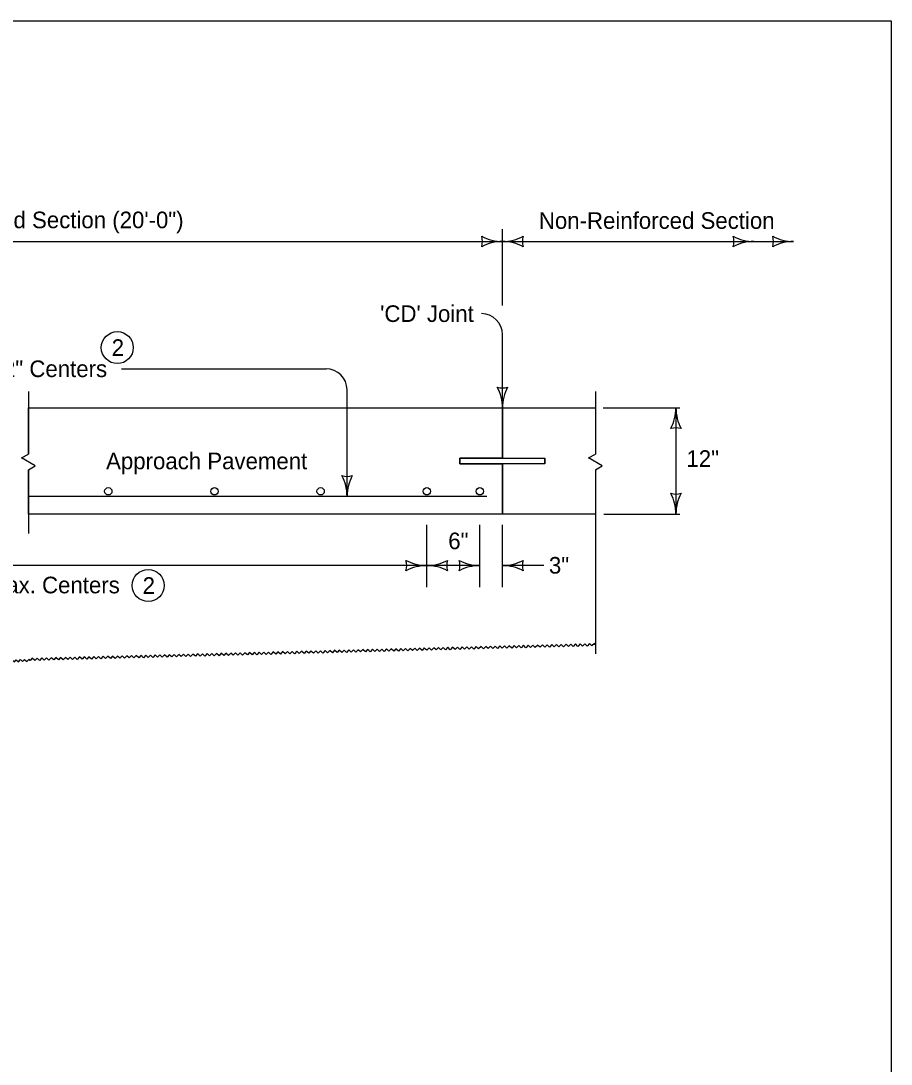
# Model space of a CAD drawing. Extents: x -2134934 to -2124557, y -2139046 to -2134021.
# Drawn here: x -2132638 to -2131799, y -2138041 to -2137036 of the extents above; entities that cross this region are included whole.
import ezdxf

# ---------------------------------------------------------------- set-up
doc = ezdxf.new("R2010")
doc.units = 0
for name, color, linetype in [('BridgeSuperStructureExisting', 7, 'Continuous'), ('dsnAlignmentStation', 7, 'Continuous'), ('dsnCellElements', 7, 'Continuous'), ('dsnStdLabel', 7, 'Continuous')]:
    doc.layers.add(name, color=color, linetype=linetype)

msp = doc.modelspace()

# ---------------------------------------------------------------- linework, layer by layer
at = {"layer": 'BridgeSuperStructureExisting'}
for p, q in [((-2132630.7, -2137393.1), (-2132630.7, -2137453.2)), ((-2132084.4, -2137393.1), (-2132084.4, -2137453.2)), ((-2132174, -2137457.1), (-2132174, -2137408.7)), ((-2132214.9, -2137462.7), (-2132214.9, -2137457.1)), ((-2132214.9, -2137457.1), (-2132133.1, -2137457.1)), ((-2132133.1, -2137457.1), (-2132133.1, -2137462.7)), ((-2132630.7, -2137468.3), (-2132630.7, -2137529.9)), ((-2132133.1, -2137462.7), (-2132214.9, -2137462.7)), ((-2132174, -2137511), (-2132174, -2137462.7)), ((-2132084.4, -2137468.3), (-2132084.4, -2137645.6)), ((-2132189.1, -2137494), (-2132630.7, -2137494))]:
    msp.add_line(p, q, dxfattribs=at)
for points in [[(-2132630.7, -2137468.3), (-2132624.1, -2137464.6), (-2132637.3, -2137457), (-2132630.7, -2137453.2)], [(-2132084.4, -2137468.3), (-2132077.9, -2137464.6), (-2132091, -2137457), (-2132084.4, -2137453.2)]]:
    msp.add_lwpolyline(points, dxfattribs=at)
for centre, radius in [((-2132545.1, -2137350.7), 15.4), ((-2132553.8, -2137489.1), 3.55), ((-2132451.5, -2137489.1), 3.55), ((-2132349.2, -2137489.1), 3.55), ((-2132246.9, -2137489.1), 3.55), ((-2132195.8, -2137489.1), 3.55), ((-2132515.3, -2137579.9), 15.4)]:
    msp.add_circle(centre, radius, dxfattribs=at)
for centre, radius, start, end in [((-2132049.3, -2137408.7), 42.5, 331.9275, 360), ((-2132049.3, -2137408.7), 42.5, 331.9275, 360), ((-2131964.3, -2137408.7), 42.5, 180, 208.0725), ((-2131964.3, -2137408.7), 42.5, 180, 208.0725), ((-2132006.8, -2137444.4), 16.4, 72.2666, 107.7334), ((-2132006.8, -2137444.4), 16.4, 72.2666, 107.7334), ((-2132006.8, -2137475.4), 16.4, 252.2666, 287.7333), ((-2132049.3, -2137511), 42.5, 360, 28.0725), ((-2131964.3, -2137511), 42.5, 151.9275, 180)]:
    msp.add_arc(centre, radius, start, end, dxfattribs=at)
at = {"layer": 'dsnAlignmentStation'}
msp.add_lwpolyline([(-2134934.4, -2137035.9), (-2131799.4, -2137035.9), (-2131799.4, -2139045.9), (-2134934.4, -2139045.9)], close=True, dxfattribs=at)
at = {"layer": 'dsnCellElements'}
for centre, radius, start, end in [((-2132209.6, -2137248.5), 16.4, 342.2666, 17.7333), ((-2132174, -2137206), 42.5, 241.9275, 270), ((-2132174, -2137291), 42.5, 90, 118.0725), ((-2132174, -2137206), 42.5, 270, 298.0725), ((-2132174, -2137291), 42.5, 61.9275, 90), ((-2132138.4, -2137248.5), 16.4, 162.2666, 197.7334), ((-2131967.3, -2137248.5), 16.4, 342.2666, 17.7333), ((-2131931.7, -2137206), 42.5, 241.9275, 270), ((-2131931.7, -2137291), 42.5, 90, 118.0725), ((-2131929.2, -2137248.5), 16.4, 342.2666, 17.7333), ((-2131893.5, -2137206), 42.5, 241.9275, 270), ((-2131893.5, -2137291), 42.5, 90, 118.0725), ((-2132174, -2137373.1), 16.4, 252.2666, 287.7333), ((-2132216.5, -2137408.7), 42.5, 360, 28.0725), ((-2132131.5, -2137408.7), 42.5, 151.9275, 180), ((-2132323.7, -2137458.4), 16.4, 252.2666, 287.7333), ((-2132366.2, -2137494), 42.5, 360, 28.0725), ((-2132281.2, -2137494), 42.5, 151.9275, 180), ((-2132282.6, -2137560.7), 16.4, 342.2666, 17.7333), ((-2132246.9, -2137518.2), 42.5, 241.9275, 270), ((-2132246.9, -2137518.2), 42.5, 270, 298.0725), ((-2132211.3, -2137560.7), 16.4, 162.2666, 197.7334), ((-2132231.4, -2137560.7), 16.4, 342.2666, 17.7333), ((-2132195.8, -2137518.2), 42.5, 241.9275, 270), ((-2132174, -2137518.2), 42.5, 270, 298.0725), ((-2132138.4, -2137560.7), 16.4, 162.2666, 197.7334), ((-2132246.9, -2137603.2), 42.5, 90, 118.0725), ((-2132246.9, -2137603.2), 42.5, 61.9275, 90), ((-2132195.8, -2137603.2), 42.5, 90, 118.0725), ((-2132174, -2137603.2), 42.5, 61.9275, 90)]:
    msp.add_arc(centre, radius, start, end, dxfattribs=at)
at = {"layer": 'dsnStdLabel'}
for p, q in [((-2132174, -2137310.2), (-2132174, -2137236.5)), ((-2133142.6, -2137248.5), (-2132174, -2137248.5)), ((-2132174, -2137248.5), (-2131893.5, -2137248.5)), ((-2132174, -2137408.7), (-2132174, -2137338.2)), ((-2132541, -2137371.1), (-2132343.9, -2137371.1)), ((-2132323.7, -2137494), (-2132323.7, -2137391.3)), ((-2132630.7, -2137453.2), (-2132630.7, -2137408.7)), ((-2132630.7, -2137408.7), (-2132174, -2137408.7)), ((-2132630.7, -2137408.7), (-2132174, -2137408.7)), ((-2132174, -2137408.7), (-2132174, -2137457.1)), ((-2132174, -2137408.7), (-2132084.9, -2137408.7)), ((-2132076.8, -2137408.7), (-2132003, -2137408.7)), ((-2132006.8, -2137408.7), (-2132006.8, -2137511)), ((-2132630.7, -2137453.2), (-2132630.7, -2137453.2)), ((-2132174, -2137457.1), (-2132214.9, -2137457.1)), ((-2132214.9, -2137457.1), (-2132214.9, -2137462.7)), ((-2132214.9, -2137457.1), (-2132214.9, -2137462.7)), ((-2132133.1, -2137462.7), (-2132133.1, -2137457.1)), ((-2132630.7, -2137511), (-2132630.7, -2137468.3)), ((-2132214.9, -2137462.7), (-2132174, -2137462.7)), ((-2132174, -2137462.7), (-2132174, -2137511)), ((-2132174, -2137511), (-2132174, -2137462.7)), ((-2132174, -2137511), (-2132630.7, -2137511)), ((-2132174, -2137511), (-2132630.7, -2137511)), ((-2132084.4, -2137511), (-2132174, -2137511)), ((-2132076.3, -2137511), (-2132003, -2137511)), ((-2132246.9, -2137581.5), (-2132246.9, -2137521.5)), ((-2132195.8, -2137581.5), (-2132195.8, -2137521.5)), ((-2132174, -2137581.5), (-2132174, -2137521.5)), ((-2132246.9, -2137560.7), (-2133069.7, -2137560.7)), ((-2132195.8, -2137560.7), (-2132246.9, -2137560.7)), ((-2132134.2, -2137560.7), (-2132174, -2137560.7))]:
    msp.add_line(p, q, dxfattribs=at)
for points in [[(-2132630.7, -2137468.3), (-2132624.1, -2137464.6), (-2132637.3, -2137457), (-2132630.7, -2137453.2)], [(-2132248.1, -2137641.2), (-2132249.3, -2137640), (-2132251.5, -2137642.4), (-2132253.8, -2137640.2), (-2132256, -2137642.5), (-2132258.4, -2137640.3), (-2132260.6, -2137642.6), (-2132262.9, -2137640.4), (-2132265.1, -2137642.7), (-2132267.5, -2137640.5), (-2132269.7, -2137642.8), (-2132272, -2137640.6), (-2132274.2, -2137643), (-2132276.6, -2137640.8), (-2132278.8, -2137643.1), (-2132281.1, -2137640.9), (-2132283.3, -2137643.2), (-2132285.7, -2137641), (-2132287.9, -2137643.3), (-2132290.2, -2137641.1), (-2132292.4, -2137643.4), (-2132294.8, -2137641.2), (-2132297, -2137643.6), (-2132299.3, -2137641.3), (-2132301.5, -2137643.7), (-2132302.7, -2137642.6)], [(-2132193.5, -2137639.7), (-2132194.6, -2137638.6), (-2132196.9, -2137640.9), (-2132199.2, -2137638.7), (-2132201.4, -2137641.1), (-2132203.8, -2137638.9), (-2132206, -2137641.2), (-2132208.3, -2137639), (-2132210.5, -2137641.3), (-2132212.9, -2137639.1), (-2132215.1, -2137641.4), (-2132217.4, -2137639.2), (-2132219.6, -2137641.5), (-2132222, -2137639.3), (-2132224.2, -2137641.7), (-2132226.5, -2137639.4), (-2132228.7, -2137641.8), (-2132231.1, -2137639.6), (-2132233.3, -2137641.9), (-2132235.6, -2137639.7), (-2132237.8, -2137642), (-2132240.2, -2137639.8), (-2132242.4, -2137642.1), (-2132244.7, -2137639.9), (-2132246.9, -2137642.2), (-2132248.1, -2137641.2)], [(-2132138.9, -2137638.3), (-2132140, -2137637.2), (-2132142.3, -2137639.5), (-2132144.6, -2137637.3), (-2132146.8, -2137639.6), (-2132149.1, -2137637.4), (-2132151.4, -2137639.8), (-2132153.7, -2137637.5), (-2132155.9, -2137639.9), (-2132158.2, -2137637.7), (-2132160.5, -2137640), (-2132162.8, -2137637.8), (-2132165, -2137640.1), (-2132167.4, -2137637.9), (-2132169.6, -2137640.2), (-2132171.9, -2137638), (-2132174.1, -2137640.3), (-2132176.4, -2137638.1), (-2132178.7, -2137640.5), (-2132181, -2137638.3), (-2132183.2, -2137640.6), (-2132185.5, -2137638.4), (-2132187.8, -2137640.7), (-2132190.1, -2137638.5), (-2132192.3, -2137640.8), (-2132193.5, -2137639.7)], [(-2132084.3, -2137636.9), (-2132085.4, -2137635.8), (-2132087.7, -2137638.1), (-2132090, -2137635.9), (-2132092.2, -2137638.2), (-2132094.5, -2137636), (-2132096.8, -2137638.3), (-2132099.1, -2137636.1), (-2132101.3, -2137638.5), (-2132103.6, -2137636.2), (-2132105.9, -2137638.6), (-2132108.2, -2137636.4), (-2132110.4, -2137638.7), (-2132112.7, -2137636.5), (-2132115, -2137638.8), (-2132117.3, -2137636.6), (-2132119.5, -2137638.9), (-2132121.8, -2137636.7), (-2132124.1, -2137639), (-2132126.4, -2137636.8), (-2132128.6, -2137639.2), (-2132130.9, -2137637), (-2132133.2, -2137639.3), (-2132135.5, -2137637.1), (-2132137.7, -2137639.4), (-2132138.9, -2137638.3)], [(-2132575.7, -2137649.7), (-2132576.9, -2137648.6), (-2132579.1, -2137650.9), (-2132581.5, -2137648.7), (-2132583.7, -2137651), (-2132586, -2137648.8), (-2132588.2, -2137651.2), (-2132590.6, -2137649), (-2132592.8, -2137651.3), (-2132595.1, -2137649.1), (-2132597.3, -2137651.4), (-2132599.7, -2137649.2), (-2132601.9, -2137651.5), (-2132604.2, -2137649.3), (-2132606.4, -2137651.6), (-2132608.8, -2137649.4), (-2132611, -2137651.8), (-2132613.3, -2137649.5), (-2132615.5, -2137651.9), (-2132617.9, -2137649.7), (-2132620.1, -2137652), (-2132622.4, -2137649.8), (-2132624.6, -2137652.1), (-2132627, -2137649.9), (-2132629.2, -2137652.2), (-2132630.3, -2137651.1)], [(-2132521.1, -2137648.3), (-2132522.3, -2137647.2), (-2132524.5, -2137649.5), (-2132526.8, -2137647.3), (-2132529.1, -2137649.6), (-2132531.4, -2137647.4), (-2132533.6, -2137649.7), (-2132535.9, -2137647.5), (-2132538.2, -2137649.9), (-2132540.5, -2137647.6), (-2132542.7, -2137650), (-2132545, -2137647.8), (-2132547.3, -2137650.1), (-2132549.6, -2137647.9), (-2132551.8, -2137650.2), (-2132554.1, -2137648), (-2132556.4, -2137650.3), (-2132558.7, -2137648.1), (-2132560.9, -2137650.5), (-2132563.2, -2137648.2), (-2132565.5, -2137650.6), (-2132567.8, -2137648.4), (-2132570, -2137650.7), (-2132572.4, -2137648.5), (-2132574.6, -2137650.8), (-2132575.7, -2137649.7)], [(-2132466.5, -2137646.8), (-2132467.7, -2137645.7), (-2132469.9, -2137648.1), (-2132472.2, -2137645.9), (-2132474.5, -2137648.2), (-2132476.8, -2137646), (-2132479, -2137648.3), (-2132481.3, -2137646.1), (-2132483.6, -2137648.4), (-2132485.9, -2137646.2), (-2132488.1, -2137648.6), (-2132490.4, -2137646.3), (-2132492.7, -2137648.7), (-2132495, -2137646.5), (-2132497.2, -2137648.8), (-2132499.5, -2137646.6), (-2132501.8, -2137648.9), (-2132504.1, -2137646.7), (-2132506.3, -2137649), (-2132508.6, -2137646.8), (-2132510.9, -2137649.1), (-2132513.2, -2137646.9), (-2132515.4, -2137649.3), (-2132517.7, -2137647.1), (-2132520, -2137649.4), (-2132521.1, -2137648.3)], [(-2132411.9, -2137645.4), (-2132413.1, -2137644.3), (-2132415.3, -2137646.6), (-2132417.6, -2137644.4), (-2132419.8, -2137646.8), (-2132422.2, -2137644.6), (-2132424.4, -2137646.9), (-2132426.7, -2137644.7), (-2132428.9, -2137647), (-2132431.3, -2137644.8), (-2132433.5, -2137647.1), (-2132435.8, -2137644.9), (-2132438, -2137647.2), (-2132440.4, -2137645), (-2132442.6, -2137647.4), (-2132444.9, -2137645.2), (-2132447.1, -2137647.5), (-2132449.5, -2137645.3), (-2132451.7, -2137647.6), (-2132454, -2137645.4), (-2132456.3, -2137647.7), (-2132458.6, -2137645.5), (-2132460.8, -2137647.8), (-2132463.1, -2137645.6), (-2132465.4, -2137648), (-2132466.5, -2137646.8)], [(-2132357.3, -2137644), (-2132358.5, -2137642.9), (-2132360.7, -2137645.2), (-2132363, -2137643), (-2132365.2, -2137645.3), (-2132367.6, -2137643.1), (-2132369.8, -2137645.5), (-2132372.1, -2137643.2), (-2132374.3, -2137645.6), (-2132376.7, -2137643.4), (-2132378.9, -2137645.7), (-2132381.2, -2137643.5), (-2132383.4, -2137645.8), (-2132385.8, -2137643.6), (-2132388, -2137645.9), (-2132390.3, -2137643.7), (-2132392.5, -2137646.1), (-2132394.9, -2137643.8), (-2132397.1, -2137646.2), (-2132399.4, -2137644), (-2132401.6, -2137646.3), (-2132404, -2137644.1), (-2132406.2, -2137646.4), (-2132408.5, -2137644.2), (-2132410.7, -2137646.5), (-2132411.9, -2137645.4)], [(-2132302.7, -2137642.6), (-2132303.9, -2137641.5), (-2132306.1, -2137643.8), (-2132308.4, -2137641.6), (-2132310.6, -2137643.9), (-2132313, -2137641.7), (-2132315.2, -2137644), (-2132317.5, -2137641.8), (-2132319.7, -2137644.2), (-2132322.1, -2137641.9), (-2132324.3, -2137644.3), (-2132326.6, -2137642.1), (-2132328.8, -2137644.4), (-2132331.2, -2137642.2), (-2132333.4, -2137644.5), (-2132335.7, -2137642.3), (-2132337.9, -2137644.6), (-2132340.3, -2137642.4), (-2132342.5, -2137644.7), (-2132344.8, -2137642.5), (-2132347, -2137644.9), (-2132349.4, -2137642.7), (-2132351.6, -2137645), (-2132353.9, -2137642.8), (-2132356.1, -2137645.1), (-2132357.3, -2137644)], [(-2132667, -2137652.9), (-2132666.2, -2137652), (-2132664.1, -2137653.9), (-2132662.2, -2137651.9), (-2132660.2, -2137653.8), (-2132658.2, -2137651.8), (-2132656.2, -2137653.7), (-2132654.3, -2137651.7), (-2132652.2, -2137653.6), (-2132650.3, -2137651.6), (-2132648.3, -2137653.5), (-2132646.3, -2137651.5), (-2132644.3, -2137653.4), (-2132642.4, -2137651.4), (-2132640.3, -2137653.3), (-2132638.4, -2137651.3), (-2132636.4, -2137653.2), (-2132634.4, -2137651.2), (-2132632.4, -2137653.1), (-2132630.5, -2137651), (-2132629.5, -2137652)]]:
    msp.add_lwpolyline(points, dxfattribs=at)
for centre in [(-2132194.2, -2137338.2), (-2132343.9, -2137391.3)]:
    msp.add_arc(centre, 20.2, 0, 90, dxfattribs=at)

# ---------------------------------------------------------------- texts
for s, p in [('Single Reinforced Section (20\'-0")', (-2132802.1, -2137235.7)), ('Non-Reinforced Section', (-2132138.9, -2137236.3)), ("'CD' Joint", (-2132291.8, -2137326)), ('2', (-2132550.5, -2137358.7)), ('#5 Bars At 12" Centers', (-2132773, -2137379.1)), ('12"', (-2131996.7, -2137465.6)), ('Approach Pavement', (-2132555.9, -2137467.9)), ('6"', (-2132226.2, -2137544.9)), ('3"', (-2132129.2, -2137568.4)), ('#5 Bars At 12" max. Centers', (-2132813.1, -2137587.4)), ('2', (-2132520.7, -2137587.9))]:
    msp.add_text(s, height=16, dxfattribs=at).set_placement(p)

doc.saveas('drawing.dxf')
